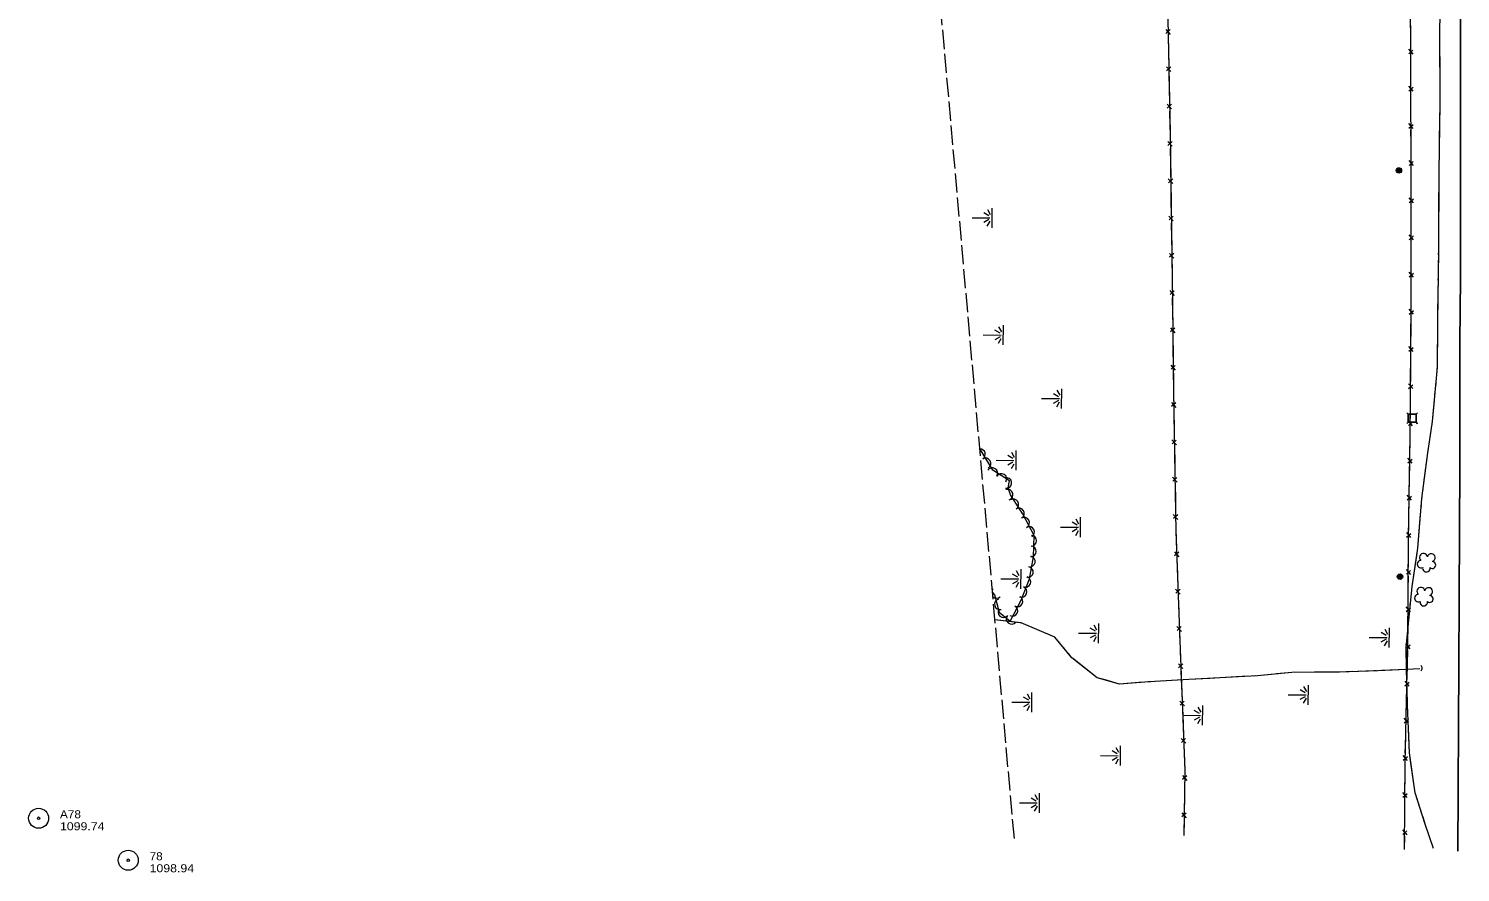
# Model space of a CAD drawing. Extents: x 296583 to 298831, y 44522 to 45957.
# Drawn here: x 296604 to 297677, y 44633 to 45266 of the extents above; entities that cross this region are included whole.
import ezdxf

# ---------------------------------------------------------------- set-up
doc = ezdxf.new("R2010")
doc.units = 0
doc.header["$LTSCALE"] = 2.4
doc.linetypes.add('LONG_DASHED', pattern=[7.5, 6, -1.5])
for name, color, linetype, lineweight in [('11', 7, 'Continuous', 25), ('14', 7, 'Continuous', 13), ('15', 7, 'Continuous', 13), ('18', 7, 'Continuous', 13), ('19', 7, 'Continuous', 13), ('21', 7, 'Continuous', 25), ('4', 7, 'Continuous', 13), ('6', 7, 'Continuous', 13)]:
    doc.layers.add(name, color=color, linetype=linetype, lineweight=lineweight)

msp = doc.modelspace()

# ---------------------------------------------------------------- linework, layer by layer
at = {"layer": '11'}
msp.add_lwpolyline([(297675.528, 44649.334), (297675.691, 44693.964), (297676.032, 44744.91), (297676.205, 44787.754), (297676.511, 44839.168), (297676.631, 44888.742), (297676.817, 44938.581), (297676.965, 44979.985), (297677.058, 45030.744), (297677.313, 45078.511), (297677.316, 45121.455), (297677.336, 45173.683), (297677.324, 45228.283), (297677.318, 45281.197)], dxfattribs=at)
at = {"layer": '14'}
for centre, radius in [((297631.282, 45159.442), 2.018), ((297631.269, 45159.439), 1.518), ((297631.309, 45159.445), 1.008), ((297631.299, 45159.449), 0.502), ((297632.097, 44854.967), 2.018), ((297632.084, 44854.964), 1.518), ((297632.124, 44854.97), 1.008), ((297632.114, 44854.974), 0.502)]:
    msp.add_circle(centre, radius, dxfattribs=at)
at = {"layer": '15'}
for p, q in [((297640.094, 45263.445), (297640.064, 45273.404)), ((297456.533, 45265.148), (297459.852, 45261.475)), ((297459.788, 45265.036), (297456.655, 45262.171)), ((297458.378, 45259.736), (297458.584, 45248.37)), ((297640.128, 45252.122), (297640.094, 45263.445)), ((297458.584, 45248.37), (297458.766, 45238.374)), ((297641.883, 45246.704), (297638.633, 45250.412)), ((297638.643, 45246.864), (297641.806, 45249.67)), ((297457.041, 45237.177), (297460.361, 45233.505)), ((297460.296, 45237.066), (297457.164, 45234.201)), ((297640.178, 45235.579), (297640.148, 45245.538)), ((297458.886, 45231.765), (297459.093, 45220.399)), ((297640.212, 45224.255), (297640.178, 45235.579)), ((297459.093, 45220.399), (297459.275, 45210.403)), ((297641.967, 45218.837), (297638.716, 45222.546)), ((297638.727, 45218.998), (297641.89, 45221.804)), ((297640.261, 45207.713), (297640.231, 45217.672)), ((297457.55, 45209.207), (297460.87, 45205.534)), ((297460.805, 45209.095), (297457.673, 45206.23)), ((297640.296, 45196.389), (297640.261, 45207.713)), ((297459.395, 45203.795), (297459.602, 45192.429)), ((297642.051, 45190.971), (297638.8, 45194.679)), ((297638.811, 45191.132), (297641.974, 45193.938)), ((297640.345, 45179.847), (297640.315, 45189.806)), ((297458.033, 45181.243), (297461.337, 45177.556)), ((297461.287, 45181.118), (297458.143, 45178.266)), ((297459.855, 45175.823), (297460.014, 45164.456)), ((297640.379, 45168.523), (297640.345, 45179.847)), ((297460.014, 45164.456), (297460.154, 45154.459)), ((297642.135, 45163.105), (297638.884, 45166.813)), ((297638.895, 45163.266), (297642.058, 45166.072)), ((297458.424, 45153.27), (297461.729, 45149.584)), ((297461.679, 45153.145), (297458.534, 45150.293)), ((297640.437, 45140.657), (297640.418, 45151.981)), ((297460.247, 45147.851), (297460.406, 45136.484)), ((297460.406, 45136.484), (297460.546, 45126.487)), ((297642.185, 45135.237), (297638.939, 45138.949)), ((297638.945, 45135.401), (297642.112, 45138.203)), ((297640.464, 45124.114), (297640.448, 45134.074)), ((297458.816, 45125.297), (297462.12, 45121.611)), ((297462.07, 45125.172), (297458.926, 45122.32)), ((297460.638, 45119.878), (297460.797, 45108.511)), ((297640.483, 45112.791), (297640.464, 45124.114)), ((297460.797, 45108.511), (297460.937, 45098.514)), ((297642.232, 45107.37), (297638.986, 45111.083)), ((297638.992, 45107.535), (297642.159, 45110.337)), ((297640.511, 45096.248), (297640.494, 45106.207)), ((297459.208, 45097.325), (297462.512, 45093.638)), ((297462.462, 45097.2), (297459.318, 45094.348)), ((297461.03, 45091.905), (297461.189, 45080.539)), ((297640.53, 45084.925), (297640.511, 45096.248)), ((297642.278, 45079.504), (297639.032, 45083.217)), ((297639.038, 45079.669), (297642.205, 45082.471)), ((297640.558, 45068.382), (297640.541, 45078.341)), ((297459.589, 45069.354), (297462.89, 45065.664)), ((297462.844, 45069.225), (297459.697, 45066.376)), ((297461.407, 45063.932), (297461.555, 45052.566)), ((297638.992, 45051.817), (297642.186, 45054.589)), ((297642.231, 45051.622), (297639.02, 45055.365)), ((297461.555, 45052.566), (297461.686, 45042.568)), ((297640.404, 45040.516), (297640.482, 45050.475)), ((297459.955, 45041.381), (297463.256, 45037.691)), ((297463.209, 45041.252), (297460.062, 45038.404)), ((297461.772, 45035.959), (297461.921, 45024.593)), ((297640.315, 45029.193), (297640.404, 45040.516)), ((297461.921, 45024.593), (297462.052, 45014.595)), ((297638.773, 45023.952), (297641.967, 45026.724)), ((297642.011, 45023.756), (297638.801, 45027.5)), ((297640.185, 45012.651), (297640.263, 45022.61)), ((297460.321, 45013.408), (297463.622, 45009.718)), ((297463.575, 45013.28), (297460.428, 45010.431)), ((297640.095, 45001.328), (297640.185, 45012.651)), ((297462.138, 45007.987), (297462.287, 44996.62)), ((297462.287, 44996.62), (297462.418, 44986.622)), ((297638.554, 44996.087), (297641.747, 44998.858)), ((297641.792, 44995.891), (297638.582, 44999.634)), ((297639.965, 44984.786), (297640.044, 44994.744)), ((297460.687, 44985.435), (297463.988, 44981.745)), ((297463.941, 44985.307), (297460.794, 44982.458)), ((297639.876, 44973.462), (297639.965, 44984.786)), ((297638.335, 44968.221), (297641.528, 44970.993)), ((297641.573, 44968.026), (297638.363, 44971.769)), ((297462.693, 44968.647), (297462.875, 44958.651)), ((297461.151, 44957.454), (297464.47, 44953.782)), ((297464.406, 44957.343), (297461.273, 44954.478)), ((297462.995, 44952.043), (297463.202, 44940.677)), ((297639.527, 44945.599), (297639.713, 44956.921)), ((297463.202, 44940.677), (297463.384, 44930.68)), ((297637.941, 44940.371), (297641.158, 44943.115)), ((297641.178, 44940.148), (297637.999, 44943.918)), ((297639.256, 44929.058), (297639.419, 44939.016)), ((297461.659, 44929.484), (297464.979, 44925.811)), ((297464.914, 44929.372), (297461.782, 44926.507)), ((297639.071, 44917.736), (297639.256, 44929.058)), ((297463.504, 44924.072), (297463.711, 44912.706)), ((297637.485, 44912.508), (297640.702, 44915.252)), ((297640.721, 44912.285), (297637.543, 44916.055)), ((297463.711, 44912.706), (297463.893, 44902.709)), ((297638.8, 44901.196), (297638.963, 44911.153)), ((297462.168, 44901.513), (297465.488, 44897.84)), ((297465.423, 44901.401), (297462.29, 44898.536)), ((297638.614, 44889.874), (297638.8, 44901.196)), ((297464.29, 44884.737), (297464.641, 44874.745)), ((297637.028, 44884.646), (297640.245, 44887.39)), ((297640.265, 44884.423), (297637.086, 44888.193)), ((297638.457, 44873.332), (297638.515, 44883.291)), ((297462.937, 44873.519), (297466.318, 44869.904)), ((297466.193, 44873.463), (297463.109, 44870.545)), ((297638.392, 44862.008), (297638.457, 44873.332)), ((297464.873, 44868.14), (297465.272, 44856.779)), ((297465.272, 44856.779), (297465.623, 44846.787)), ((297636.861, 44856.764), (297640.049, 44859.542)), ((297640.1, 44856.575), (297636.882, 44860.312)), ((297638.296, 44845.466), (297638.354, 44855.425)), ((297463.918, 44845.561), (297467.3, 44841.945)), ((297467.175, 44845.505), (297464.091, 44842.587)), ((297465.855, 44840.182), (297466.254, 44828.821)), ((297638.231, 44834.143), (297638.296, 44845.466)), ((297636.7, 44828.898), (297639.888, 44831.677)), ((297639.939, 44828.71), (297636.721, 44832.446)), ((297466.254, 44828.821), (297466.604, 44818.829)), ((297638.135, 44817.6), (297638.193, 44827.559)), ((297464.9, 44817.603), (297468.282, 44813.987)), ((297468.157, 44817.547), (297465.073, 44814.629)), ((297466.841, 44812.224), (297467.277, 44800.864)), ((297638.07, 44806.277), (297638.135, 44817.6)), ((297467.277, 44800.864), (297467.661, 44790.873)), ((297636.453, 44801.061), (297639.691, 44803.781)), ((297639.687, 44800.813), (297636.538, 44804.608)), ((297637.68, 44789.739), (297637.921, 44799.695)), ((297465.961, 44789.642), (297469.354, 44786.037)), ((297469.217, 44789.596), (297466.143, 44786.669)), ((297637.407, 44778.419), (297637.68, 44789.739)), ((297467.915, 44784.269), (297468.351, 44772.909)), ((297635.78, 44773.203), (297639.018, 44775.922)), ((297639.015, 44772.955), (297635.866, 44776.75)), ((297468.351, 44772.909), (297468.735, 44762.918)), ((297637.007, 44761.881), (297637.248, 44771.837)), ((297467.034, 44761.687), (297470.428, 44758.083)), ((297470.291, 44761.642), (297467.217, 44758.714)), ((297468.988, 44756.314), (297469.425, 44744.955)), ((297636.734, 44750.561), (297637.007, 44761.881)), ((297469.425, 44744.955), (297469.808, 44734.964)), ((297635.107, 44745.345), (297638.346, 44748.064)), ((297638.342, 44745.097), (297635.193, 44748.892)), ((297636.335, 44734.023), (297636.575, 44743.979)), ((297468.108, 44733.733), (297471.501, 44730.128)), ((297471.365, 44733.687), (297468.291, 44730.759)), ((297636.061, 44722.702), (297636.335, 44734.023)), ((297470.062, 44728.359), (297470.498, 44717)), ((297634.435, 44717.487), (297637.673, 44720.206)), ((297637.669, 44717.239), (297634.52, 44721.034)), ((297468.986, 44705.869), (297472.182, 44702.088)), ((297472.236, 44705.649), (297469.01, 44702.89)), ((297635.793, 44694.838), (297635.848, 44706.162)), ((297470.651, 44700.399), (297470.48, 44689.032)), ((297634.267, 44689.593), (297637.453, 44692.374)), ((297637.506, 44689.407), (297634.285, 44693.14)), ((297470.48, 44689.032), (297470.33, 44679.035)), ((297635.713, 44678.296), (297635.761, 44688.255)), ((297468.566, 44677.897), (297471.762, 44674.116)), ((297471.816, 44677.677), (297468.59, 44674.918)), ((297470.231, 44672.427), (297470.06, 44661.06)), ((297635.659, 44666.973), (297635.713, 44678.296)), ((297634.133, 44661.727), (297637.318, 44664.508)), ((297637.372, 44661.541), (297634.15, 44665.274)), ((297635.579, 44650.43), (297635.627, 44660.389))]:
    msp.add_line(p, q, dxfattribs=at)
for points in [[(297457.426, 45332.288), (297458.134, 45273.124), (297459.691, 45187.524), (297461.194, 45080.187), (297462.548, 44976.644), (297464.144, 44888.893), (297466.789, 44813.574), (297470.787, 44709.482), (297470.06, 44661.06)], [(297635.579, 44650.43), (297635.894, 44715.773), (297638.067, 44805.759), (297638.519, 44884.052), (297639.777, 44960.845), (297640.569, 45061.514), (297640.403, 45160.692), (297639.979, 45301.513), (297559.293, 45317.144), (297507.689, 45326.082), (297485.682, 45330.454)], [(297459.602, 45192.429), (297459.691, 45187.524), (297459.762, 45182.432)], [(297640.418, 45151.981), (297640.403, 45160.692), (297640.399, 45161.94)], [(297461.189, 45080.539), (297461.194, 45080.187), (297461.32, 45070.541)], [(297640.534, 45057.059), (297640.569, 45061.514), (297640.558, 45068.382)], [(297462.504, 44980.014), (297462.548, 44976.644), (297462.693, 44968.647)], [(297639.713, 44956.921), (297639.777, 44960.845), (297639.824, 44966.879)], [(297464.013, 44896.101), (297464.144, 44888.893), (297464.29, 44884.737)], [(297470.498, 44717), (297470.787, 44709.482), (297470.75, 44707.007)], [(297635.848, 44706.162), (297635.894, 44715.773), (297635.902, 44716.121)]]:
    msp.add_lwpolyline(points, dxfattribs=at)
msp.add_arc((297646.314, 44786.432), 2.41, 305.45253, 51.69209, dxfattribs=at)
at = {"layer": '18'}
msp.add_lwpolyline([(297326.661, 44843.143), (297328.184, 44841.369), (297331.503, 44828.391), (297339.808, 44821.607), (297348.153, 44837.302), (297354.403, 44853.449), (297357.337, 44869.758), (297357.877, 44885.779), (297348.998, 44902.285), (297340.158, 44916.407), (297338.474, 44921.503), (297339.376, 44926.754), (297326.971, 44934.704), (297317.282, 44950.636), (297317.133, 44950.722)], dxfattribs=at)
for centre, radius, start, end in [((297317.243, 44946.669), 4.002, 301.31342, 91.50392), ((297321.401, 44939.832), 4.002, 301.31342, 121.29809), ((297326.453, 44932.548), 4.002, 327.35304, 147.33772), ((297333.191, 44928.23), 4.002, 327.35304, 147.33772), ((297336.973, 44925.138), 4.002, 260.2607, 80.24538), ((297337.952, 44916.408), 4.002, 288.29407, 108.27875), ((297342.261, 44909.1), 4.002, 302.05314, 122.03782), ((297346.507, 44902.317), 4.002, 302.05314, 122.03782), ((297350.306, 44895.433), 4.002, 298.28461, 118.26929), ((297354.097, 44888.385), 4.002, 298.28461, 118.26929), ((297355.652, 44881.935), 4.002, 268.07719, 88.06187), ((297355.382, 44873.937), 4.002, 268.07719, 88.06187), ((297649.692, 44869.372), 2.974, 7.98733, 229.22121), ((297655.544, 44869.216), 2.975, 285.63814, 168.61141), ((297353.17, 44858.422), 4.002, 259.8092, 79.79388), ((297354.586, 44866.298), 4.002, 259.8092, 79.79388), ((297647.796, 44864.344), 2.777, 90.95822, 298.73121), ((297651.849, 44861.313), 2.783, 167.63523, 8.64628), ((297656.267, 44863.742), 2.611, 230.34337, 88.27598), ((297351.249, 44851.103), 4.002, 248.84779, 68.83247), ((297324.474, 44848.91), 4.002, 299.73313, 310.62346), ((297329.685, 44842.836), 4.002, 130.63879, 143.29118), ((297345.356, 44836.504), 4.002, 242.00817, 61.99285), ((297348.36, 44843.64), 4.002, 248.84779, 68.83247), ((297645.846, 44838.87), 2.777, 90.95822, 298.73121), ((297647.742, 44843.898), 2.974, 7.98733, 229.22121), ((297653.594, 44843.742), 2.975, 285.63814, 168.61141), ((297654.317, 44838.268), 2.611, 230.34337, 88.27598), ((297329.685, 44842.836), 4.002, 226.83156, 310.62346), ((297332.162, 44834.267), 4.002, 104.35304, 284.33772), ((297334.744, 44828.448), 4.002, 140.76374, 320.74842), ((297341.6, 44829.438), 4.002, 242.00817, 61.99285), ((297649.899, 44835.839), 2.783, 167.63523, 8.64628), ((297340.941, 44823.386), 4.002, 140.76374, 320.74842)]:
    msp.add_arc(centre, radius, start, end, dxfattribs=at)
at = {"layer": '19'}
for p, q in [((297662.035, 45255.607), (297662.024, 45257.756)), ((297662.067, 45249.159), (297662.056, 45251.308)), ((297662.241, 45213.695), (297662.088, 45244.86)), ((297661.71, 45176.087), (297661.745, 45178.236)), ((297661.498, 45163.192), (297661.533, 45165.341)), ((297661.604, 45169.639), (297661.639, 45171.789)), ((297322.824, 45130.178), (297324.886, 45126.477)), ((297326.295, 45116.511), (297326.407, 45131.305)), ((297311.282, 45124.05), (297324.701, 45123.948)), ((297323.921, 45122.579), (297320.054, 45120.408)), ((297323.942, 45125.384), (297320.109, 45127.613)), ((297322.729, 45117.803), (297324.847, 45121.472)), ((297660.977, 45090.119), (297661.007, 45092.268)), ((297660.793, 45077.224), (297660.823, 45079.373)), ((297660.885, 45083.672), (297660.915, 45085.821)), ((297319.651, 45036.169), (297333.07, 45036.067)), ((297332.29, 45034.698), (297328.423, 45032.527)), ((297332.311, 45037.503), (297328.478, 45039.732)), ((297331.098, 45029.922), (297333.216, 45033.591)), ((297331.193, 45042.297), (297333.255, 45038.596)), ((297334.664, 45028.63), (297334.776, 45043.424)), ((297659.464, 45004.185), (297659.656, 45006.325)), ((297376.058, 44989.847), (297372.225, 44992.076)), ((297374.94, 44994.641), (297377.002, 44990.94)), ((297378.411, 44980.974), (297378.523, 44995.768)), ((297658.316, 44991.341), (297658.507, 44993.481)), ((297658.89, 44997.763), (297659.082, 44999.903)), ((297363.398, 44988.513), (297376.817, 44988.411)), ((297376.037, 44987.042), (297372.17, 44984.871)), ((297374.845, 44982.266), (297376.963, 44985.935)), ((297340.856, 44948.349), (297342.918, 44944.648)), ((297344.327, 44934.682), (297344.439, 44949.476)), ((297329.314, 44942.221), (297342.733, 44942.119)), ((297341.953, 44940.75), (297338.086, 44938.579)), ((297341.974, 44943.555), (297338.141, 44945.784)), ((297340.761, 44935.974), (297342.879, 44939.643)), ((297649.247, 44918.932), (297649.521, 44921.06)), ((297647.925, 44906.121), (297648.105, 44908.261)), ((297390.21, 44893.535), (297386.377, 44895.764)), ((297389.092, 44898.329), (297391.154, 44894.628)), ((297392.563, 44884.662), (297392.675, 44899.456)), ((297377.55, 44892.201), (297390.969, 44892.099)), ((297390.189, 44890.73), (297386.322, 44888.559)), ((297388.997, 44885.954), (297391.115, 44889.623)), ((297332.861, 44853.37), (297346.28, 44853.268)), ((297345.5, 44851.899), (297341.633, 44849.728)), ((297345.521, 44854.704), (297341.688, 44856.933)), ((297344.308, 44847.123), (297346.426, 44850.792)), ((297344.403, 44859.498), (297346.465, 44855.797)), ((297347.874, 44845.831), (297347.986, 44860.625)), ((297639.164, 44827.204), (297639.371, 44829.342)), ((297639.786, 44833.62), (297639.994, 44835.759)), ((297347.213, 44820.459), (297328.476, 44822.65)), ((297402.627, 44818.826), (297404.689, 44815.125)), ((297406.098, 44805.159), (297406.21, 44819.953)), ((297638.541, 44820.787), (297638.749, 44822.926)), ((297391.085, 44812.698), (297404.504, 44812.596)), ((297403.724, 44811.227), (297399.857, 44809.056)), ((297403.745, 44814.032), (297399.912, 44816.261)), ((297402.532, 44806.451), (297404.65, 44810.12)), ((297609.064, 44809.483), (297622.483, 44809.381)), ((297621.703, 44808.012), (297617.836, 44805.841)), ((297621.724, 44810.817), (297617.891, 44813.046)), ((297620.606, 44815.611), (297622.668, 44811.91)), ((297624.077, 44801.944), (297624.189, 44816.738)), ((297377.272, 44804.872), (297376.014, 44806.388)), ((297381.047, 44800.324), (297379.788, 44801.84)), ((297384.821, 44795.775), (297383.563, 44797.291)), ((297620.511, 44803.236), (297622.629, 44806.905)), ((297451.075, 44776.536), (297449.108, 44776.424)), ((297456.977, 44776.871), (297455.01, 44776.759)), ((297523.872, 44780.624), (297521.904, 44780.515)), ((297529.761, 44781.127), (297527.8, 44780.941)), ((297535.647, 44781.685), (297533.685, 44781.499)), ((297602.569, 44784.029), (297600.6, 44783.955)), ((297608.476, 44784.251), (297606.507, 44784.177)), ((297614.383, 44784.472), (297612.414, 44784.398)), ((297637.594, 44760.57), (297637.022, 44785.424)), ((297352.642, 44767.136), (297354.704, 44763.435)), ((297356.113, 44753.469), (297356.225, 44768.263)), ((297548.33, 44766.498), (297561.749, 44766.396)), ((297560.969, 44765.027), (297557.102, 44762.856)), ((297560.99, 44767.832), (297557.157, 44770.061)), ((297559.872, 44772.626), (297561.934, 44768.925)), ((297563.343, 44758.959), (297563.455, 44773.753)), ((297341.1, 44761.008), (297354.519, 44760.906)), ((297353.739, 44759.537), (297349.872, 44757.366)), ((297353.76, 44762.342), (297349.927, 44764.571)), ((297352.547, 44754.761), (297354.665, 44758.43)), ((297481.724, 44752.424), (297477.891, 44754.653)), ((297480.606, 44757.218), (297482.668, 44753.517)), ((297484.077, 44743.551), (297484.189, 44758.345)), ((297559.777, 44760.251), (297561.895, 44763.92)), ((297637.775, 44755.432), (297637.701, 44757.144)), ((297469.064, 44751.09), (297482.483, 44750.988)), ((297481.703, 44749.619), (297477.836, 44747.448)), ((297480.511, 44744.843), (297482.629, 44748.512)), ((297637.995, 44750.297), (297637.922, 44752.008)), ((297638.216, 44745.161), (297638.142, 44746.873)), ((297420.183, 44722.234), (297416.35, 44724.463)), ((297419.065, 44727.028), (297421.127, 44723.327)), ((297422.536, 44713.361), (297422.648, 44728.155)), ((297407.523, 44720.9), (297420.942, 44720.798)), ((297420.162, 44719.429), (297416.295, 44717.258)), ((297418.97, 44714.653), (297421.088, 44718.322)), ((297358.283, 44691.599), (297360.345, 44687.898)), ((297361.754, 44677.932), (297361.866, 44692.726)), ((297346.741, 44685.471), (297360.16, 44685.369)), ((297359.38, 44684), (297355.513, 44681.829)), ((297359.401, 44686.805), (297355.568, 44689.034)), ((297358.188, 44679.224), (297360.306, 44682.893)), ((297645.272, 44687.637), (297644.764, 44689.258)), ((297646.798, 44682.773), (297646.289, 44684.394)), ((297648.323, 44677.91), (297647.815, 44679.531))]:
    msp.add_line(p, q, dxfattribs=at)
for points in [[(297637.022, 44785.424), (297636.698, 44801.791), (297641.15, 44847.674), (297645.424, 44876.366), (297648.541, 44913.442), (297652.967, 44947.856), (297656.52, 44971.259), (297660.168, 45012.052), (297660.349, 45046.158), (297661.101, 45098.817), (297661.419, 45158.422), (297662.261, 45209.566), (297661.996, 45263.55), (297662.357, 45289.249), (297661.583, 45299.637)], [(297662.003, 45262.055), (297661.996, 45263.55), (297662.005, 45264.204)], [(297661.816, 45182.534), (297662.261, 45209.566), (297662.241, 45213.695)], [(297661.255, 45127.73), (297661.419, 45158.422), (297661.427, 45158.894)], [(297661.069, 45096.566), (297661.101, 45098.817), (297661.255, 45127.73)], [(297660.326, 45041.764), (297660.349, 45046.158), (297660.731, 45072.926)], [(297660.039, 45010.607), (297660.168, 45012.052), (297660.326, 45041.764)], [(297654.227, 44956.157), (297656.52, 44971.259), (297657.933, 44987.059)], [(297650.068, 44925.318), (297652.967, 44947.856), (297654.227, 44956.157)], [(297648.465, 44912.54), (297648.541, 44913.442), (297648.699, 44914.674)], [(297644.604, 44870.861), (297645.424, 44876.366), (297647.566, 44901.841)], [(297640.409, 44840.037), (297641.15, 44847.674), (297644.604, 44870.861)], [(297646.862, 44785.896), (297637.022, 44785.424), (297615.523, 44784.515), (297586.635, 44783.431), (297550.974, 44783.139), (297525.266, 44780.701), (297497.1, 44779.145), (297473.709, 44777.823), (297443.945, 44776.13), (297421.773, 44774.525), (297405.069, 44779.258), (297386.175, 44794.143), (297373.302, 44809.657), (297348.103, 44820.355), (297328.476, 44822.65)], [(297373.498, 44809.421), (297373.302, 44809.657), (297348.103, 44820.355), (297347.213, 44820.459)], [(297637.022, 44785.424), (297636.698, 44801.791), (297638.126, 44816.51)], [(297411.164, 44777.531), (297405.069, 44779.258), (297387.605, 44793.017)], [(297439.275, 44775.792), (297421.773, 44774.525), (297411.164, 44777.531)], [(297445.173, 44776.2), (297443.945, 44776.13), (297443.206, 44776.077)], [(297489.439, 44778.712), (297473.709, 44777.823), (297460.912, 44777.095)], [(297517.969, 44780.298), (297497.1, 44779.145), (297489.439, 44778.712)], [(297568.096, 44783.279), (297550.974, 44783.139), (297539.571, 44782.058)], [(297596.662, 44783.807), (297586.635, 44783.431), (297568.096, 44783.279)], [(297646.862, 44785.896), (297637.022, 44785.424), (297618.32, 44784.633)], [(297657.143, 44651.198), (297650.977, 44669.449), (297643.572, 44693.057), (297639.17, 44722.943), (297637.641, 44758.544), (297637.022, 44785.424)], [(297640.047, 44716.99), (297639.17, 44722.943), (297638.363, 44741.737)], [(297643.747, 44692.5), (297643.572, 44693.057), (297640.047, 44716.99)], [(297657.143, 44651.198), (297650.977, 44669.449), (297649.34, 44674.667)]]:
    msp.add_lwpolyline(points, dxfattribs=at)
at = {"layer": '21'}
for p, q in [((297638.208, 44970.736), (297637.139, 44969.685)), ((297638.254, 44976.736), (297637.202, 44977.805)), ((297645.26, 44969.622), (297644.207, 44970.69)), ((297645.323, 44977.743), (297644.253, 44976.691))]:
    msp.add_line(p, q, dxfattribs=at)
msp.add_lwpolyline([(297644.207, 44970.69), (297644.253, 44976.691), (297638.254, 44976.736), (297638.208, 44970.736)], close=True, dxfattribs=at)
at = {"layer": '4', "linetype": 'LONG_DASHED'}
msp.add_line((297342.991, 44658.77), (297236.947, 45856.087), dxfattribs=at)
at = {"layer": '6'}
for centre, radius in [((296611.597, 44673.893), 7.5), ((296611.597, 44673.893), 0.96), ((296678.775, 44642.426), 7.5), ((296678.775, 44642.426), 0.96)]:
    msp.add_circle(centre, radius, dxfattribs=at)

# ---------------------------------------------------------------- texts
for s, width, p in [('A78', 1.1, (296627.597, 44673.893)), ('1099.74', 1.15, (296627.597, 44664.893)), ('78', 1.1, (296694.775, 44642.426)), ('1098.94', 1.15, (296694.775, 44633.426))]:
    msp.add_text(s, height=6, dxfattribs=dict(at, width=width)).set_placement(p)

doc.saveas('drawing.dxf')
